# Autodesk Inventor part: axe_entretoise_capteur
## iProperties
Created: 2011-01
Part Number: axe_entretoise_capteur
Document SubType Name: Modeling
Designer: eric
Density: 1 g/cm^3
Mass: 2.59775 g
Surface Area: 12.4175 cm^2
Volume: 2.59775 cm^3
Author: eric
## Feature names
1. Base1
